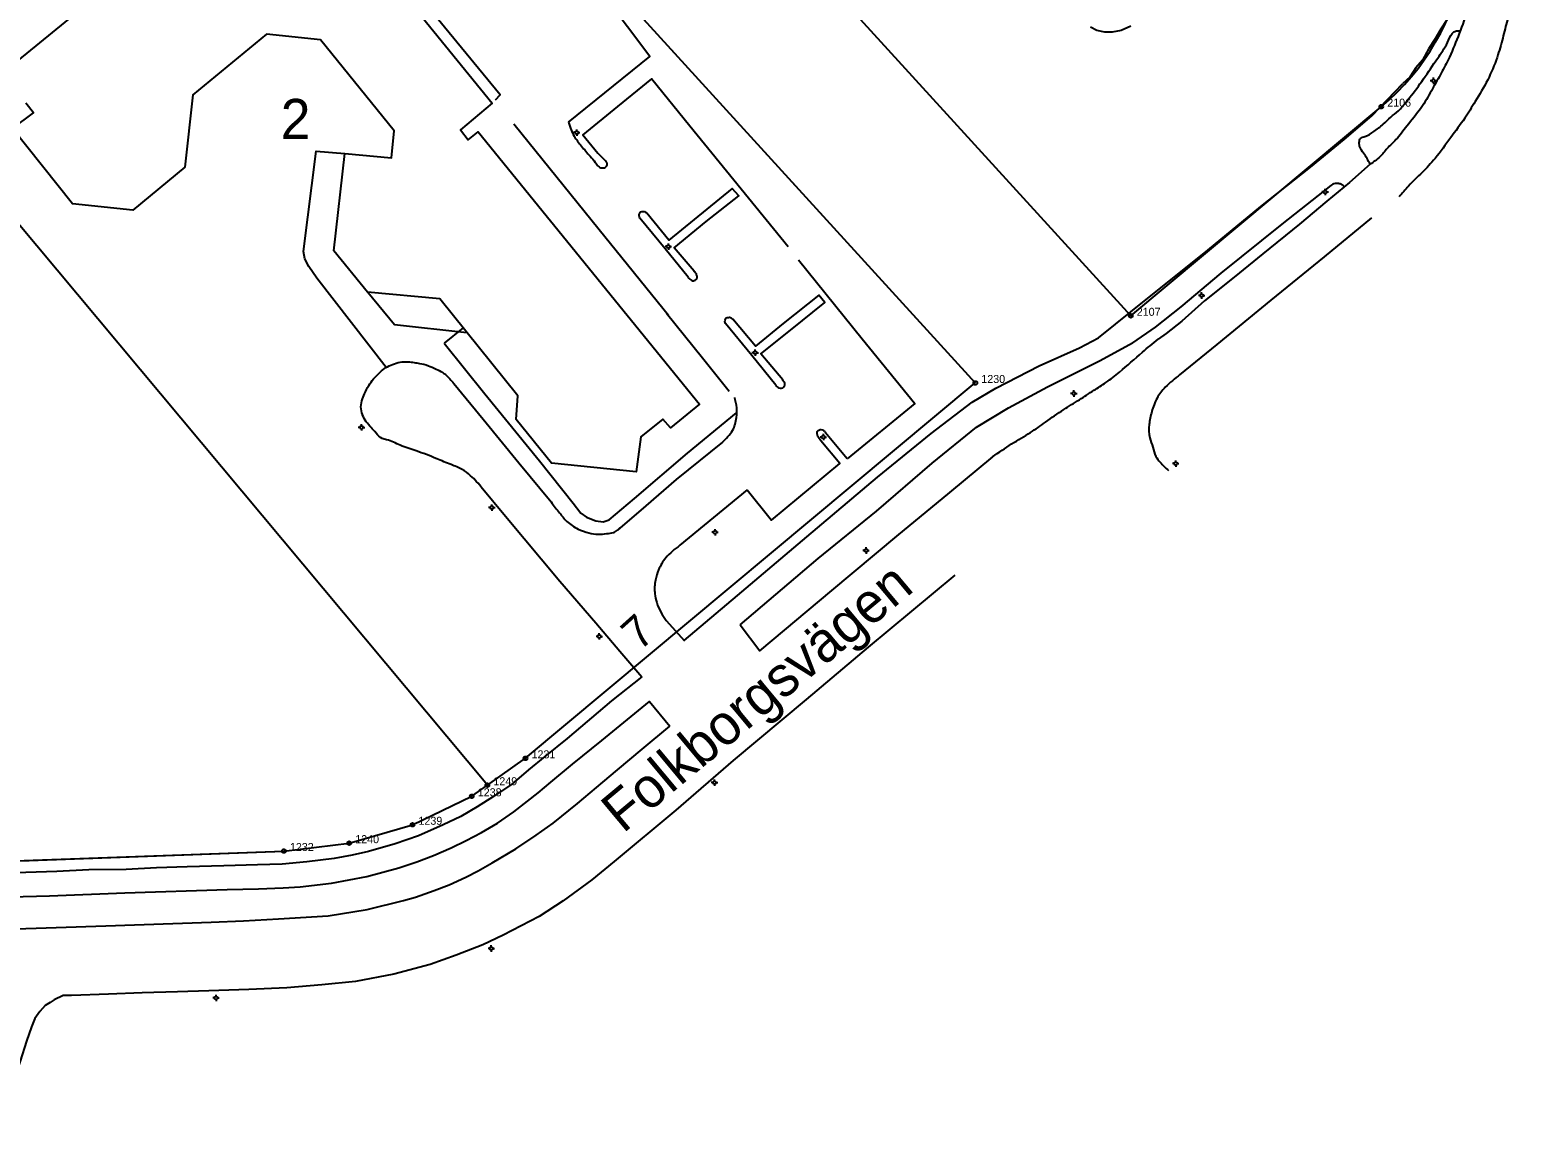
# Model space of a CAD drawing. Extents: x 1517693 to 1518189, y 6494860 to 6495280.
# Drawn here: x 1517936.6 to 1518123.3, y 6494924.9 to 6495063.4 of the extents above; entities that cross this region are included whole.
import ezdxf

# ---------------------------------------------------------------- set-up
doc = ezdxf.new("R2010")
doc.units = 0
for name, color, linetype in [('adress', 7, 'Continuous'), ('allmanbyggnad', 7, 'Continuous'), ('fastighetsbeteckning', 7, 'Continuous'), ('gatunamn', 7, 'Continuous'), ('gc_vag', 7, 'Continuous'), ('grans', 7, 'Continuous'), ('granspunkt', 7, 'Continuous'), ('granspunkt_text', 7, 'Continuous'), ('kvartersgrans', 7, 'Continuous'), ('kvartersgrans_utan_fastgr', 7, 'Continuous'), ('parkeringskant', 7, 'Continuous'), ('planteringskant', 7, 'Continuous'), ('stolpe_belysning', 7, 'Continuous'), ('trappa_byggnad', 7, 'Continuous'), ('vagkant', 7, 'Continuous'), ('vagkant_mindre', 7, 'Continuous')]:
    doc.layers.add(name, color=color, linetype=linetype)

msp = doc.modelspace()

# ---------------------------------------------------------------- linework, layer by layer
at = {"layer": 'allmanbyggnad'}
msp.add_lwpolyline([(1517931.88, 6495057.02), (1517968.08, 6495086.54), (1517994.34, 6495054.25), (1517990.35, 6495050.91), (1517991.33, 6495049.66), (1517992.59, 6495050.68), (1518020.21, 6495016.65), (1518016.6, 6495013.68), (1518015.65, 6495014.78), (1518012.9, 6495012.57), (1518012.33, 6495008.18), (1518001.72, 6495009.28), (1517997.31, 6495014.75), (1517997.53, 6495017.68), (1517987.77, 6495029.81), (1517978.76, 6495030.65), (1517974.55, 6495035.81), (1517975.91, 6495047.99), (1517981.76, 6495047.42), (1517982.09, 6495050.79), (1517972.88, 6495062.16), (1517966.11, 6495062.88), (1517956.9, 6495055.28), (1517955.93, 6495046.27), (1517949.41, 6495040.9), (1517941.88, 6495041.67), (1517934.38, 6495051.09), (1517937.03, 6495053.07), (1517936.06, 6495054.26)], dxfattribs=at)
at = {"layer": 'gc_vag'}
for points in [[(1518108.04, 6495066.38), (1518111.18, 6495065.48), (1518113.3, 6495064.86), (1518113.64, 6495064.7), (1518112.86, 6495063.49), (1518112.15, 6495062.31), (1518111.37, 6495061.1), (1518110.56, 6495059.64), (1518109.72, 6495058.67), (1518108.98, 6495057.52), (1518108.11, 6495056.71)], [(1518070.06, 6495024.95), (1518076.25, 6495029.91), (1518083.28, 6495035.51), (1518090.37, 6495041.36), (1518096.55, 6495046.25), (1518100.78, 6495049.7), (1518104.23, 6495052.69), (1518108.11, 6495056.71)], [(1517981.09, 6495021.24), (1517972.4, 6495032.38), (1517971.41, 6495033.86), (1517970.92, 6495034.79), (1517970.73, 6495035.72), (1517972.34, 6495048.28), (1517975.91, 6495047.99)], [(1518099.11, 6495043.98), (1518092.97, 6495039.15), (1518085.36, 6495033.03), (1518080.35, 6495028.8), (1518077.16, 6495026.26), (1518074.33, 6495024.31)], [(1518049.18, 6495012.98), (1518054.3, 6495016.9), (1518057.26, 6495018.64), (1518062.65, 6495021.42), (1518067.69, 6495023.69), (1518070.06, 6495024.95)], [(1518049.31, 6495009.27), (1518054.82, 6495013.77), (1518058.82, 6495016.21), (1518063.69, 6495018.82), (1518070.3, 6495022.12), (1518074.33, 6495024.31)], [(1518018.32, 6494987.11), (1518024.97, 6494992.73), (1518033.63, 6495000.09), (1518042.48, 6495007.51), (1518049.18, 6495012.98)], [(1518025.3, 6494989.09), (1518035.06, 6494997.36), (1518042.35, 6495003.28), (1518049.31, 6495009.27)], [(1518013.01, 6494982.59), (1518009.23, 6494979.59), (1518003.7, 6494974.86), (1518000.89, 6494972.62), (1517998.86, 6494970.97), (1517996.76, 6494969.18), (1517994.49, 6494967.61), (1517992.45, 6494966.34)], [(1518004.36, 6494971.67), (1518008.04, 6494974.61), (1518013.96, 6494979.52), (1518016.53, 6494976.42)], [(1517982.65, 6494958.71), (1517984.89, 6494959.48), (1517986.99, 6494960.25), (1517989.2, 6494961.23), (1517991.09, 6494962.14), (1517992.98, 6494963.12), (1517994.98, 6494964.31), (1517997.04, 6494965.71), (1517998.72, 6494967.04), (1518000.05, 6494968.1), (1518001.63, 6494969.43), (1518004.36, 6494971.67)], [(1517992.45, 6494966.34), (1517990.41, 6494965.15), (1517988.2, 6494964.07), (1517985.12, 6494962.73), (1517982.21, 6494961.72), (1517978.86, 6494960.74)], [(1517978.86, 6494960.74), (1517976.83, 6494960.32), (1517974.59, 6494959.9), (1517971.16, 6494959.48), (1517968.08, 6494959.19)], [(1517939.93, 6494958.28), (1517936.05, 6494958.14), (1517929.92, 6494957.93), (1517923.68, 6494957.69), (1517915.87, 6494957.44)], [(1517968.08, 6494959.19), (1517964.98, 6494959.09), (1517960.81, 6494958.98), (1517956.22, 6494958.84), (1517952.37, 6494958.7), (1517948.59, 6494958.53), (1517943.93, 6494958.46), (1517939.93, 6494958.28)], [(1517961.19, 6494956.01), (1517965.13, 6494956.08), (1517968.22, 6494956.22), (1517970.32, 6494956.36), (1517974.24, 6494956.81), (1517978.65, 6494957.65), (1517982.65, 6494958.71)], [(1517907.22, 6494954.18), (1517920.7, 6494954.64), (1517929.14, 6494954.95), (1517938.99, 6494955.23)], [(1517938.99, 6494955.23), (1517948.44, 6494955.58), (1517961.19, 6494956.01)]]:
    msp.add_lwpolyline(points, dxfattribs=at)
for points in [[(1518104.03, 6495046.64), (1518103.2, 6495048.02), (1518102.76, 6495048.73), (1518102.66, 6495049.33), (1518102.82, 6495049.85), (1518103.37, 6495050.09), (1518104.49, 6495050.72), (1518105.66, 6495051.63), (1518106.59, 6495052.5), (1518107.55, 6495053.3), (1518108.56, 6495054.45), (1518110.25, 6495056.66), (1518112, 6495059.2), (1518113.24, 6495061.03), (1518113.82, 6495062.13), (1518114.48, 6495063.17), (1518114.93, 6495063.3), (1518115.29, 6495063.32)], [(1518100.81, 6495043.84), (1518100.4, 6495044.12), (1518099.93, 6495044.23), (1518099.36, 6495044.12), (1518099.11, 6495043.98)]]:
    msp.add_spline(points, degree=3, dxfattribs=at)
at = {"layer": 'grans'}
for p, q in [((1517942.78, 6495142.01), (1518054.69, 6495019.3)), ((1517993.72, 6494969.04), (1517919.72, 6495057.58)), ((1517998.49, 6494972.4), (1518054.69, 6495019.3)), ((1517993.72, 6494969.04), (1517998.49, 6494972.4)), ((1517984.36, 6494964.1), (1517991.77, 6494967.66)), ((1517991.77, 6494967.66), (1517993.72, 6494969.04)), ((1517976.46, 6494961.8), (1517984.36, 6494964.1)), ((1517968.3, 6494960.82), (1517976.46, 6494961.8)), ((1517845.48, 6494956.3), (1517968.3, 6494960.82))]:
    msp.add_line(p, q, dxfattribs=at)
at = {"layer": 'granspunkt'}
for centre in [(1518105.41, 6495053.82), (1518074.11, 6495027.69), (1518054.69, 6495019.3), (1517998.49, 6494972.4), (1517993.72, 6494969.04), (1517991.77, 6494967.66), (1517984.36, 6494964.1), (1517976.46, 6494961.8), (1517968.3, 6494960.82)]:
    msp.add_circle(centre, 0.237, dxfattribs=at)
at = {"layer": 'kvartersgrans'}
msp.add_line((1517998.49, 6494972.4), (1518054.69, 6495019.3), dxfattribs=at)
for points in [[(1517905.68, 6495182.68), (1517942.78, 6495142.01), (1518054.69, 6495019.3)], [(1517991.77, 6494967.66), (1517993.72, 6494969.04), (1517998.49, 6494972.4)], [(1517810.53, 6494961.99), (1517821.9, 6494958.56), (1517833.61, 6494956.65), (1517845.48, 6494956.3), (1517968.3, 6494960.82), (1517976.46, 6494961.8), (1517984.36, 6494964.1), (1517991.77, 6494967.66)]]:
    msp.add_lwpolyline(points, dxfattribs=at)
at = {"layer": 'kvartersgrans_utan_fastgr'}
for p, q in [((1517921.04, 6495195.52), (1518074.11, 6495027.69)), ((1518074.11, 6495027.69), (1518105.41, 6495053.82))]:
    msp.add_line(p, q, dxfattribs=at)
msp.add_arc((1518086.18, 6495076.85), 30.01, 309.8505, 350.4132, dxfattribs=at)
at = {"layer": 'parkeringskant'}
msp.add_line((1518038.68, 6495009.83), (1518035.97, 6495013.08), dxfattribs=at)
for points in [[(1517994.73, 6495054.69), (1517995.32, 6495055.28), (1517988.37, 6495063.76), (1517982.21, 6495071.32), (1517974.72, 6495080.46), (1517969.13, 6495087.4), (1517968.08, 6495086.54)], [(1518003.87, 6495051.87), (1518014.03, 6495060.08), (1518005.76, 6495071.07), (1518004.81, 6495070.32)], [(1518031.29, 6495036.3), (1518025.43, 6495043.52), (1518019, 6495051.38), (1518014.23, 6495057.31), (1518009.99, 6495053.83), (1518005.66, 6495050.31), (1518007.51, 6495048), (1518008.31, 6495047.2)], [(1518016.35, 6495027.72), (1518007.68, 6495038.45), (1517997.01, 6495051.64)], [(1518019.55, 6495033.25), (1518017.07, 6495036.17), (1518021.07, 6495039.48), (1518025.15, 6495042.66), (1518024.32, 6495043.59), (1518016.4, 6495037.16), (1518013.66, 6495040.51)], [(1518018.79, 6495032.52), (1518015.94, 6495036.07), (1518012.79, 6495039.88)], [(1518032.61, 6495034.68), (1518040.56, 6495024.81), (1518047.12, 6495016.72), (1518038.68, 6495009.83)], [(1518030.63, 6495019.67), (1518027.91, 6495022.92), (1518031.59, 6495025.9), (1518035.89, 6495029.34), (1518035.13, 6495030.27), (1518030.69, 6495026.73), (1518027.22, 6495023.88), (1518024.37, 6495027.26)], [(1518029.77, 6495019.01), (1518026.75, 6495022.75), (1518023.47, 6495026.73)], [(1518026.19, 6495005.95), (1518029.24, 6495002.14), (1518037.78, 6495009.23), (1518035.4, 6495012.08)]]:
    msp.add_lwpolyline(points, dxfattribs=at)
for points in [[(1518003.87, 6495051.87), (1518004.2, 6495050.91), (1518004.56, 6495050.15), (1518005.49, 6495048.89), (1518006.55, 6495047.63), (1518007.21, 6495046.84), (1518007.58, 6495046.37), (1518008.01, 6495046.17), (1518008.44, 6495046.24), (1518008.64, 6495046.44), (1518008.64, 6495046.84), (1518008.31, 6495047.2)], [(1518012.79, 6495039.88), (1518012.7, 6495040.18), (1518012.75, 6495040.5), (1518012.87, 6495040.67), (1518013.17, 6495040.73), (1518013.48, 6495040.66), (1518013.66, 6495040.51)], [(1518018.79, 6495032.52), (1518019.26, 6495032.1), (1518019.67, 6495032.13), (1518019.88, 6495032.32), (1518019.92, 6495032.63), (1518019.78, 6495033), (1518019.55, 6495033.25)], [(1518023.47, 6495026.73), (1518023.41, 6495026.98), (1518023.46, 6495027.28), (1518023.56, 6495027.44), (1518023.83, 6495027.49), (1518024.09, 6495027.49), (1518024.24, 6495027.38), (1518024.37, 6495027.26)], [(1518029.77, 6495019.01), (1518030.14, 6495018.68), (1518030.48, 6495018.67), (1518030.74, 6495018.77), (1518030.87, 6495019.04), (1518030.88, 6495019.29), (1518030.76, 6495019.5), (1518030.63, 6495019.67)], [(1518035.4, 6495012.08), (1518035.02, 6495012.62), (1518034.91, 6495012.95), (1518034.94, 6495013.22), (1518035.04, 6495013.36), (1518035.4, 6495013.47), (1518035.73, 6495013.36), (1518035.97, 6495013.08)]]:
    msp.add_spline(points, degree=3, dxfattribs=at)
at = {"layer": 'planteringskant'}
msp.add_line((1517990.69, 6495026.18), (1517988.32, 6495024.26), dxfattribs=at)
for points in [[(1518074.11, 6495063.87), (1518072.93, 6495063.32), (1518071.79, 6495063.11), (1518070.88, 6495063.14), (1518069.86, 6495063.32), (1518069.07, 6495063.74)], [(1517988.32, 6495024.26), (1517993.4, 6495017.96), (1518000.23, 6495009.56), (1518004.46, 6495004.29)], [(1518004.46, 6495004.29), (1518005.4, 6495003.05), (1518006.12, 6495002.53), (1518007.29, 6495002.07), (1518008.2, 6495001.94), (1518008.92, 6495002.2), (1518012.11, 6495004.87), (1518018.74, 6495010.54), (1518024.86, 6495015.55)]]:
    msp.add_lwpolyline(points, dxfattribs=at)
at = {"layer": 'stolpe_belysning'}
for p, q in [((1518111.74, 6495057.05), (1518111.54, 6495057.05)), ((1518111.94, 6495057.25), (1518111.94, 6495057.45)), ((1518112.14, 6495057.05), (1518112.34, 6495057.05)), ((1518111.94, 6495056.85), (1518111.94, 6495056.65)), ((1518004.69, 6495050.58), (1518004.49, 6495050.58)), ((1518004.89, 6495050.78), (1518004.89, 6495050.98)), ((1518004.89, 6495050.38), (1518004.89, 6495050.18)), ((1518005.09, 6495050.58), (1518005.29, 6495050.58)), ((1518098.2, 6495043.16), (1518098, 6495043.16)), ((1518098.4, 6495043.36), (1518098.4, 6495043.56)), ((1518098.4, 6495042.96), (1518098.4, 6495042.76)), ((1518098.6, 6495043.16), (1518098.8, 6495043.16)), ((1518016.34, 6495036.53), (1518016.34, 6495036.73)), ((1518016.14, 6495036.33), (1518015.94, 6495036.33)), ((1518016.34, 6495036.13), (1518016.34, 6495035.93)), ((1518016.54, 6495036.33), (1518016.74, 6495036.33)), ((1518082.76, 6495030.23), (1518082.56, 6495030.23)), ((1518082.96, 6495030.43), (1518082.96, 6495030.63)), ((1518082.96, 6495030.03), (1518082.96, 6495029.83)), ((1518083.16, 6495030.23), (1518083.36, 6495030.23)), ((1518027.18, 6495023.28), (1518027.18, 6495023.48)), ((1518026.98, 6495023.08), (1518026.78, 6495023.08)), ((1518027.18, 6495022.88), (1518027.18, 6495022.68)), ((1518027.38, 6495023.08), (1518027.58, 6495023.08)), ((1518066.8, 6495017.98), (1518066.6, 6495017.98)), ((1518067, 6495018.18), (1518067, 6495018.38)), ((1518067.2, 6495017.98), (1518067.4, 6495017.98)), ((1518067, 6495017.78), (1518067, 6495017.58)), ((1517977.99, 6495013.94), (1517977.99, 6495014.14)), ((1517977.79, 6495013.74), (1517977.59, 6495013.74)), ((1517977.99, 6495013.54), (1517977.99, 6495013.34)), ((1517978.19, 6495013.74), (1517978.39, 6495013.74)), ((1518035.5, 6495012.54), (1518035.3, 6495012.54)), ((1518035.7, 6495012.74), (1518035.7, 6495012.94)), ((1518035.7, 6495012.34), (1518035.7, 6495012.14)), ((1518035.9, 6495012.54), (1518036.1, 6495012.54)), ((1518079.53, 6495009.22), (1518079.33, 6495009.22)), ((1518079.73, 6495009.42), (1518079.73, 6495009.62)), ((1518079.73, 6495009.02), (1518079.73, 6495008.82)), ((1518079.93, 6495009.22), (1518080.13, 6495009.22)), ((1517994.08, 6495003.73), (1517993.88, 6495003.73)), ((1517994.28, 6495003.93), (1517994.28, 6495004.13)), ((1517994.28, 6495003.53), (1517994.28, 6495003.33)), ((1517994.48, 6495003.73), (1517994.68, 6495003.73)), ((1518022.17, 6495000.85), (1518022.17, 6495001.05)), ((1518021.97, 6495000.65), (1518021.77, 6495000.65)), ((1518022.17, 6495000.45), (1518022.17, 6495000.25)), ((1518022.37, 6495000.65), (1518022.57, 6495000.65)), ((1518040.83, 6494998.37), (1518040.63, 6494998.37)), ((1518041.03, 6494998.57), (1518041.03, 6494998.77)), ((1518041.03, 6494998.17), (1518041.03, 6494997.97)), ((1518041.23, 6494998.37), (1518041.43, 6494998.37)), ((1518007.7, 6494987.83), (1518007.7, 6494988.03)), ((1518007.5, 6494987.63), (1518007.3, 6494987.63)), ((1518007.7, 6494987.43), (1518007.7, 6494987.23)), ((1518007.9, 6494987.63), (1518008.1, 6494987.63)), ((1518021.9, 6494969.36), (1518021.7, 6494969.36)), ((1518022.1, 6494969.56), (1518022.1, 6494969.76)), ((1518022.3, 6494969.36), (1518022.5, 6494969.36)), ((1518022.1, 6494969.16), (1518022.1, 6494968.96)), ((1517994.21, 6494948.84), (1517994.21, 6494949.04)), ((1517994.01, 6494948.64), (1517993.81, 6494948.64)), ((1517994.21, 6494948.44), (1517994.21, 6494948.24)), ((1517994.41, 6494948.64), (1517994.61, 6494948.64)), ((1517959.62, 6494942.46), (1517959.42, 6494942.46)), ((1517959.82, 6494942.66), (1517959.82, 6494942.86)), ((1517959.82, 6494942.26), (1517959.82, 6494942.06)), ((1517960.02, 6494942.46), (1517960.22, 6494942.46))]:
    msp.add_line(p, q, dxfattribs=at)
for centre in [(1518111.94, 6495057.05), (1518004.89, 6495050.58), (1518098.4, 6495043.16), (1518016.34, 6495036.33), (1518082.96, 6495030.23), (1518027.18, 6495023.08), (1518067, 6495017.98), (1517977.99, 6495013.74), (1518035.7, 6495012.54), (1518079.73, 6495009.22), (1517994.28, 6495003.73), (1518022.17, 6495000.65), (1518041.03, 6494998.37), (1518007.7, 6494987.63), (1518022.1, 6494969.36), (1517994.21, 6494948.64), (1517959.82, 6494942.46)]:
    msp.add_circle(centre, 0.2, dxfattribs=at)
at = {"layer": 'trappa_byggnad'}
msp.add_lwpolyline([(1517978.79, 6495030.64), (1517982.12, 6495026.61), (1517991.15, 6495025.61)], dxfattribs=at)
at = {"layer": 'vagkant'}
for points in [[(1518104.03, 6495046.64), (1518101.43, 6495044.36), (1518098.63, 6495042.02), (1518095.18, 6495039.15), (1518090.63, 6495035.44), (1518087.05, 6495032.51), (1518083.34, 6495029.58), (1518080.48, 6495027.04), (1518078.53, 6495025.48), (1518077.52, 6495024.76)], [(1518080.24, 6495020.33), (1518084.9, 6495024.11), (1518091.67, 6495029.65), (1518098.31, 6495035.05), (1518104.23, 6495039.93)], [(1518025.31, 6494989.09), (1518027.77, 6494985.83), (1518036.75, 6494993.39), (1518044.89, 6495000.16), (1518051.52, 6495005.62), (1518056.86, 6495010.05)], [(1518052.14, 6494995.27), (1518041.28, 6494986.3), (1518033.54, 6494979.77), (1518024.45, 6494972.11)], [(1518009.97, 6494970.97), (1518013.08, 6494973.56), (1518016.53, 6494976.42)], [(1518024.45, 6494972.11), (1518017.25, 6494965.92), (1518009.56, 6494959.53)], [(1517983.24, 6494954.64), (1517984.75, 6494955.06), (1517987.09, 6494955.9), (1517988.95, 6494956.6), (1517991.02, 6494957.55), (1517992.56, 6494958.35), (1517994.34, 6494959.34), (1517997.29, 6494961.09), (1517999.81, 6494962.81), (1518001.95, 6494964.31), (1518004.99, 6494966.77), (1518008.14, 6494969.43), (1518009.97, 6494970.97)], [(1518009.56, 6494959.53), (1518006.76, 6494957.23), (1518003.19, 6494954.61), (1518000.18, 6494952.64), (1517995.69, 6494950.3)], [(1517959.2, 6494951.94), (1517963.24, 6494952.08), (1517967.62, 6494952.33), (1517973.82, 6494952.71), (1517978.69, 6494953.52), (1517983.24, 6494954.64)], [(1517907.64, 6494950.12), (1517920.28, 6494950.57), (1517928.48, 6494950.89), (1517939.83, 6494951.27)], [(1517939.83, 6494951.27), (1517946.03, 6494951.48), (1517959.2, 6494951.94)], [(1517995.69, 6494950.3), (1517993.15, 6494949.1), (1517989.83, 6494947.81), (1517986.57, 6494946.62), (1517982.02, 6494945.42), (1517977.25, 6494944.51), (1517973.02, 6494944.09), (1517968.67, 6494943.71)], [(1517968.67, 6494943.71), (1517963.93, 6494943.5), (1517958.92, 6494943.36), (1517955, 6494943.22), (1517950.58, 6494943.08), (1517946.38, 6494942.94), (1517941.76, 6494942.76), (1517940.73, 6494942.75), (1517939.59, 6494942.23)], [(1517939.59, 6494942.23), (1517939.09, 6494941.88), (1517938.46, 6494941.5), (1517937.8, 6494940.76), (1517937.17, 6494939.89), (1517936.75, 6494938.84), (1517936.12, 6494937.05), (1517935.35, 6494934.56), (1517934.79, 6494932.95), (1517934.3, 6494932.04), (1517933.66, 6494931.09), (1517933.21, 6494930.36), (1517932.26, 6494929.27), (1517931.42, 6494928.53), (1517930.55, 6494927.87), (1517929.32, 6494927.1), (1517927.89, 6494926.43), (1517926.17, 6494925.59), (1517924.72, 6494924.95)]]:
    msp.add_lwpolyline(points, dxfattribs=at)
for points in [[(1518123.26, 6495074.18), (1518122.67, 6495071.12), (1518122.02, 6495067.34), (1518121.18, 6495064.67), (1518120.59, 6495062.39), (1518119.88, 6495059.98), (1518118.71, 6495057.18), (1518117.14, 6495054.45), (1518115.84, 6495052.37), (1518114.09, 6495049.96), (1518112.13, 6495047.35), (1518110.51, 6495045.6), (1518108.82, 6495043.9), (1518107.64, 6495042.54)], [(1518117.47, 6495073), (1518116.88, 6495069.49), (1518116.1, 6495065.71), (1518115, 6495062.59), (1518113.76, 6495059.66), (1518112.78, 6495057.77), (1518111.68, 6495055.82), (1518110.38, 6495053.67), (1518108.62, 6495051.39), (1518107.25, 6495049.7), (1518106.15, 6495048.59), (1518105.24, 6495047.55), (1518104.02, 6495046.63)], [(1518056.85, 6495010.05), (1518059.23, 6495011.68), (1518061.58, 6495013.11), (1518063.46, 6495014.41), (1518065.74, 6495015.98), (1518067.69, 6495017.21), (1518069.51, 6495018.38), (1518071.01, 6495019.36), (1518072.7, 6495020.66), (1518075.57, 6495023.14), (1518077.52, 6495024.76)], [(1518080.25, 6495020.34), (1518078.43, 6495018.77), (1518077.39, 6495017.41), (1518076.74, 6495015.72), (1518076.41, 6495014.09), (1518076.48, 6495012.46), (1518076.87, 6495011.29), (1518077.26, 6495010.12), (1518077.78, 6495009.4), (1518078.82, 6495008.36)]]:
    msp.add_spline(points, degree=3, dxfattribs=at)
at = {"layer": 'vagkant_mindre'}
for p, q in [((1518026.19, 6495005.95), (1518017.78, 6494999.03)), ((1518002.79, 6494994.52), (1518007.28, 6494989.32)), ((1518016.08, 6494989.62), (1518018.36, 6494987.07))]:
    msp.add_line(p, q, dxfattribs=at)
for points in [[(1518016.11, 6495028.02), (1518020.6, 6495022.42), (1518023.95, 6495018.28)], [(1517989.53, 6495019.24), (1517993.21, 6495014.76), (1517997.64, 6495009.33), (1518001.68, 6495004.43)], [(1518023.11, 6495011.92), (1518017.32, 6495007.24), (1518013.51, 6495003.96), (1518009.97, 6495000.91)], [(1517992.94, 6495006.33), (1517996, 6495002.67), (1518002.79, 6494994.52)], [(1518007.28, 6494989.32), (1518010.26, 6494985.77), (1518013.01, 6494982.59)]]:
    msp.add_lwpolyline(points, dxfattribs=at)
for points in [[(1517978.2, 6495015.12), (1517977.94, 6495016.05), (1517978.04, 6495017.08), (1517978.37, 6495017.94), (1517978.9, 6495019), (1517979.5, 6495019.8), (1517980.32, 6495020.66), (1517981.05, 6495021.22), (1517981.88, 6495021.62), (1517982.81, 6495021.89), (1517983.8, 6495021.95), (1517984.56, 6495021.85), (1517985.23, 6495021.75), (1517986.35, 6495021.46), (1517987.31, 6495021.03), (1517988.11, 6495020.63), (1517988.47, 6495020.36), (1517989.03, 6495019.8), (1517989.53, 6495019.24)], [(1518023.08, 6495011.89), (1518024.36, 6495013.37), (1518024.84, 6495015), (1518024.88, 6495016.2), (1518024.62, 6495017.5)], [(1517993.09, 6495006.18), (1517991.63, 6495007.71), (1517990.57, 6495008.5), (1517989.18, 6495009.1), (1517987.39, 6495009.83), (1517984.81, 6495010.82), (1517982.84, 6495011.52), (1517981.12, 6495012.21), (1517980.57, 6495012.35), (1517979.83, 6495013.04), (1517978.59, 6495014.46), (1517978.12, 6495015.26)], [(1518001.68, 6495004.43), (1518002.73, 6495003.07), (1518003.66, 6495002.01), (1518005.05, 6495001.05), (1518006.4, 6495000.58), (1518007.56, 6495000.39), (1518008.62, 6495000.49), (1518009.48, 6495000.62), (1518009.98, 6495000.92), (1518010.31, 6495001.25)], [(1518017.78, 6494999.03), (1518016.01, 6494997.44), (1518015.11, 6494995.95), (1518014.72, 6494994.65), (1518014.65, 6494992.96), (1518014.88, 6494991.87), (1518015.41, 6494990.65), (1518016.08, 6494989.62)]]:
    msp.add_spline(points, degree=3, dxfattribs=at)

# ---------------------------------------------------------------- texts
at = {"layer": 'adress'}
msp.add_text('7', height=4, rotation=42.0101, dxfattribs=at).set_placement((1518012.74, 6494985.72))
at = {"layer": 'fastighetsbeteckning'}
msp.add_text('2', height=5, rotation=0.0021, dxfattribs=at).set_placement((1517967.9, 6495049.79))
at = {"layer": 'gatunamn'}
msp.add_text('Folkborgsvägen', height=5, rotation=39.8263, dxfattribs=at).set_placement((1518010.67, 6494962.94))
at = {"layer": 'granspunkt_text'}
for s, p in [('2106', (1518106.16, 6495053.82)), ('2107', (1518074.86, 6495027.69)), ('1230', (1518055.44, 6495019.3)), ('1231', (1517999.24, 6494972.4)), ('1249', (1517994.47, 6494969.04)), ('1238', (1517992.52, 6494967.66)), ('1239', (1517985.11, 6494964.1)), ('1232', (1517969.05, 6494960.82)), ('1240', (1517977.21, 6494961.8))]:
    msp.add_text(s, height=1, dxfattribs=at).set_placement(p)

doc.saveas('drawing.dxf')
